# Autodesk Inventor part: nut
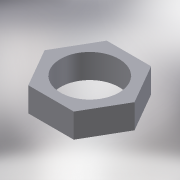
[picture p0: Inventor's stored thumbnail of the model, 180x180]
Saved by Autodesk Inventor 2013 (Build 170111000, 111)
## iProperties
Shininess: 25.0
Length Units: 11269
Angle Units: 11279
Time Units: 11290
Mass Units: 11283
Length Display Precision: 3
Angle Display Precision: 2
Created: 2002-03
Part Number: nut
Material: Steel, Mild
Document SubType Name: Modeling
Designer: =<Author>
Density: 7.86 g/cm^3
Description: =<Part Number>
Density: 7.86
Volumn: 4.343765694124716
Area: 27.312478925305754
PropertySet Name: Model Information
Control State: 0
Master: False
Checked Out: True
Last Check In Date: 2008-10-15
Checked Out Date: 2008-10-15
Author: LAlexey
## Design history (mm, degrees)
sketch "Sketch1"
  geometry: L1 (-12.648, 25.757)-(5.602, 25.757); L2 (5.602, 25.757)-(14.952, 9.561); L3 (14.952, 9.561)-(5.828, -6.243); L4 (5.828, -6.243)-(-12.873, -6.243); L5 (-12.873, -6.243)-(-21.998, 9.561); L6 (-21.998, 9.561)-(-12.648, 25.757); C1 r 12 at (-3.636, 9.757)
  constraints: 12 end point, 1 centre point, 1 equal length, 1 horizontal, 1 parallel
  dimensions: "d0" = 120 deg angle of L4 L5; "d2" = 32 distance between parallel lines of L4 L1; "d3" = 32 distance between parallel lines of L3 L6; "d4" = 32 distance between parallel lines of L2 L5; "d5" = 120 deg angle of L1 L6; "d6" = 120 deg angle of L2 L3 (derived); "d7" = 24 diameter of C1; "d8" = 16 distance from line of L1 C1.centre; "d9" = 16 distance from line of L2 C1.centre
extrude "Extrusion1" new body sketch "Sketch1" distance "d10" = 10; taper "d11" = 0 deg
body "Solid1"
other parameters: "d1" = 21.08499 (derived)
